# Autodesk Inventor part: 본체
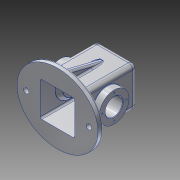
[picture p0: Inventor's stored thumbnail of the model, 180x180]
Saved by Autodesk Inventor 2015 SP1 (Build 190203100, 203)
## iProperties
Created: 2017-07
Part Number: 본체
Material: 알루미늄 6061
Document SubType Name: Modeling
Designer: C04
Density: 2.7 g/cm^3
Appearance: 알루미늄 - 평지
Mass: 889.343 g
Surface Area: 986.145 cm^2
Volume: 329.386 cm^3
Author: C04
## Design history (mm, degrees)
sketch "스케치1"
  geometry: L1 (0, 0)-(-75, 0); L2 (0, 0)-(0, 65); 1 further point; 1 other entity
  constraints: 4 end point, 1 coincident, 1 horizontal, 1 perpendicular, 4 other
  dimensions: "d32" = 75 distance of L1.start L1.end; "d33" = 65 distance of L1.start L2.end
extrude "돌출1" new body sketch "스케치1" distance "d1" = 10; taper "d2" = 0 deg
sketch "스케치7"
  geometry: L1 (-37, 37)-(37, 37); L2 (37, 37)-(37, -37); L3 (37, -37)-(-37, -37); L4 (-37, -37)-(-37, 37); L5 (-37, 37)-(37, -37); L6 (37, 37)-(-37, -37); 1 further point
  constraints: 12 end point, 2 midpoint, 2 parallel, 1 horizontal, 1 perpendicular
  dimensions: "d34" = 74 distance of L2.end L3.end; "d35" = 74 distance of L1.end L2.end
extrude "돌출6" join sketch "스케치7" distance "d36" = 100; taper "d37" = 0 deg
fillet "모깎기3" dims "d38" = 8
sketch "스케치8"
  geometry: L1 (-32, -32)-(32, -32); L2 (32, -32)-(32, 32); L3 (32, 32)-(-32, 32); L4 (-32, 32)-(-32, -32); L5 (-32, -32)-(32, 32); L6 (32, -32)-(-32, 32); 1 further point
  constraints: 12 end point, 2 midpoint, 2 parallel, 1 horizontal, 1 perpendicular
  dimensions: "d39" = 64 distance of L3.end L2.end; "d40" = 64 distance of L2.end L1.end
extrude "돌출7" cut sketch "스케치8" distance "d41" = 105; taper "d42" = 0 deg
sketch "스케치9"
  geometry: L1 (-3, -10)-(61, -10) reference; C1 r 27.5 at (29, 45); 4 further points
  constraints: 1 centre point, 1 midpoint, 1 vertical alignment
  dimensions: "d44" = 55 diameter of C1; "d45" = 55 distance from line of C1.centre L1
extrude "돌출8" join sketch "스케치9" distance "d46" = 13; taper "d47" = 0 deg
sketch "스케치10"
  geometry: L1 (-3, -10)-(61, -10) reference; C1 r 27.5 at (29, 45); 3 further points
  constraints: 1 centre point, 1 vertical alignment
  dimensions: "d48" = 55 diameter of C1; "d49" = 55 distance from line of C1.centre L1
extrude "돌출9" join sketch "스케치10" distance "d50" = 13; taper "d51" = 0 deg
fillet "모깎기5" dims "d52" = 3
sketch "스케치12"
  geometry: L1 (-32, 102)-(-32, 0) reference; L2 (32, 0)-(32, 102) reference; L3 (50, 27.5)-(50, 82.5) reference; L4 (-50, 82.5)-(-50, 27.5) reference; L5 (-32, 55)-(32, 55); L6 (25, 55)-(25, 75.5); L7 (-25, 75.5)-(-25, 55); L8 (-25, 75.5)-(-32, 82.5); L9 (25, 75.5)-(32, 82.5); L10 (29, 0)-(-29, 0) reference; 2 further points
  constraints: 10 end point, 6 point on line, 2 parallel, 1 horizontal alignment, 1 midpoint
  dimensions: "d53" = 7 distance between parallel lines of L2 L6; "d54" = 7 distance between parallel lines of L1 L7; "d55" = 55 diameter of L8.end L5; "d56" = 55 diameter of L9.end L5; "d57" = 135 deg angle of L1 L8; "d58" = 135 deg angle of L2 L9; "d59" = 55 distance between parallel lines of L5 L10 (derived)
revolve "회전2" sketch "스케치12" stored, may be unused: angle "d60" = 90 deg
fillet "모깎기6" dims "d61" = 0.5
sketch "스케치13"
  geometry: C1 r 27.5 at (0, 0) reference; 2 further points
  constraints: 1 vertical alignment
  dimensions: "d62" = 22.5 distance of point (0, 22.5) C1.centre
hole "구멍1" sketch "스케치13" at (0, 22.5) diameter "d63" = 3.242; stored, may be unused: countersink angle "d67" = 90 deg, drill point angle "d69" = 118 deg; dims "d64" = 8, "d65" = 4, "d66" = 2, "d68" = 10
sketch "스케치14"
  geometry: C1 r 20.293 at (0, 0) reference; 2 further points
  constraints: 1 vertical alignment
  dimensions: "d73" = 22.5 distance of C1.centre point (0, 22.5)
hole "구멍2" sketch "스케치14" at (0, 22.5) diameter "d74" = 3.242; stored, may be unused: countersink angle "d78" = 90 deg, drill point angle "d80" = 118 deg; dims "d75" = 8, "d76" = 4, "d77" = 2, "d79" = 10
hole "구멍3" diameter "d86" = 32; stored, may be unused: countersink angle "d90" = 90 deg, drill point angle "d92" = 0 deg; dims "d84" = 10, "d85" = 10, "d87" = 8, "d88" = 4, "d89" = 2, "d91" = 10
sketch "스케치15"
  geometry: L1 (-20, 20)-(20, 20); L2 (20, 20)-(20, -20); L3 (20, -20)-(-20, -20); L4 (-20, -20)-(-20, 20); L5 (-20, 20)-(20, -20); L6 (20, 20)-(-20, -20); 1 further point
  constraints: 12 end point, 2 midpoint, 2 parallel, 1 horizontal, 1 perpendicular
  dimensions: "d134" = 40 distance of L2.end L3.end; "d135" = 40 distance of L1.end L2.end
extrude "돌출10" join sketch "스케치15" distance "d94" = 10; taper "d95" = -5 deg
chamfer "모따기1" distance "d105" = 1; stored, may be unused: second distance "d106" = 2, angle "d107" = 45 deg
sketch "스케치17"
  geometry: 3 further points
  constraints: 2 horizontal alignment
  dimensions: "d108" = 116 distance of point (58, 0) point (-58, 0); "d109" = 58 distance of point (0, 0) point (-58, 0)
hole "구멍5" sketch "스케치17" at (-58, 0), (58, 0) diameter "d110" = 10; stored, may be unused: countersink angle "d114" = 90 deg, drill point angle "d116" = 0 deg; dims "d111" = 8, "d112" = 28, "d113" = 4, "d115" = 30
sketch "스케치18"
  geometry: L1 (10, 55)-(82.194, 37); 1 further point
  constraints: 2 end point
  dimensions: "d119" = 55.78548 distance from line of point (0, 0) L1; "d120" = 90.13802 distance of point (0, 0) L1.end; "d121" = 55.9017 distance of point (0, 0) L1.start; "d122" = 55 vertical distance of point (0, 0) L1.start
feature "리브1" sketch "스케치18" dims "d123" = 1, "d124" = 10, "d125" = 0, "d126" = 0, "d127" = 1, "d128" = 1
fillet "모깎기7" dims "d129" = 3
fillet "모깎기8" dims "d130" = 3
fillet "모깎기9" dims "d131" = 0.5
fillet "모깎기11" dims "d133" = 3
sketch "스케치19"
  geometry: 2 further points
  constraints: 1 coincident
hole "구멍6" sketch "스케치19" at (0, 0) diameter "d136" = 21; stored, may be unused: countersink angle "d140" = 90 deg, drill point angle "d142" = 0 deg; dims "d137" = 8, "d138" = 28, "d139" = 4, "d141" = 30
fillet "모깎기12" dims "d143" = 3
node "솔리드1"
pattern_circular "원형 패턴1" dims angle "d71" = 360 deg
pattern_circular "원형 패턴2" dims angle "d82" = 360 deg
mirror "대칭1"
